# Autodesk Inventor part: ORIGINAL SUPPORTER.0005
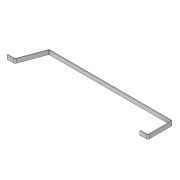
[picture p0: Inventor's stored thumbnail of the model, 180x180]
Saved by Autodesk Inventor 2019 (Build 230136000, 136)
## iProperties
Created: 2019-10
Part Number: ORIGINAL SUPPORTER.0005
Material: Generic
Document SubType Name: Sheet Metal
Designer: hp
Density: 1 g/cm^3
Sheet Metal Rule: Default_mm
Appearance: Default
Author: hp
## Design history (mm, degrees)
node "Face1"
  sketch "Sketch1"
    geometry: L1 (-53.057, 40.444)-(266.943, 40.444); L2 (266.943, 40.444)-(266.943, 30.444); L3 (266.943, 30.444)-(-53.057, 30.444); L4 (-53.057, 30.444)-(-53.057, 40.444); 1 further point
    constraints: 8 end point, 2 parallel, 1 horizontal, 1 perpendicular
    dimensions: "d3" = 320 distance of L2.end L3.end; "d4" = 10 distance of L1.end L2.end
node "Flange1"
node "Flange2"
node "Flange3"
node "Flange4"
body "Solid1"
face "Plate1" dims "d2" = 2 (= Thickness)
sketch "Sketch2"
  geometry: L1 through (-5, 0) direction (1, 0); L2 through (0, 32.5) direction (0, 1); L3 (0, 65)-(-10, 65); L4 (-10, 65)-(-10, 0)
  constraints: 6 end point, 1 horizontal, 1 perpendicular, 1 vertical
face "Plate2" dims "d2" = 2 (= Thickness), "d5" = 2 (= BendReliefWidth), "d6" = 1 (= BendReliefDepth), "d7" = 4 (= MinimumRemnant), "d8" = 2 (= TransitionRadius), "d9" = 65, "d10" = 90 deg, "d11" = 2 (= BendRadius), "d12" = 8 (= CornerReliefSize), "d13" = 2 (= GapSize), "d14" = 2 (= JacobiRadiusSize), "SeamGap" = 0.01
bend "Bend1" dims "d2" = 2 (= Thickness), "d5" = 2 (= BendReliefWidth), "d6" = 1 (= BendReliefDepth), "d7" = 4 (= MinimumRemnant), "d8" = 2 (= TransitionRadius), "d9" = 65, "d10" = 90 deg, "d11" = 2 (= BendRadius), "SeamGap" = 0.01
feature "Corner1" dims "d9" = 65, "d10" = 90 deg, "d12" = 8 (= CornerReliefSize), "d13" = 2 (= GapSize), "d14" = 2 (= JacobiRadiusSize)
sketch "Sketch3"
  geometry: L1 through (-5, 0) direction (1, 0); L2 through (0, 35) direction (0, 1); L3 (0, 70)-(-10, 70); L4 (-10, 70)-(-10, 0)
  constraints: 6 end point, 1 horizontal, 1 perpendicular, 1 vertical
face "Plate3" dims "d2" = 2 (= Thickness), "d15" = 2 (= BendReliefWidth), "d16" = 1 (= BendReliefDepth), "d17" = 4 (= MinimumRemnant), "d18" = 2 (= TransitionRadius), "d19" = 70, "d20" = 70 deg, "d21" = 2 (= BendRadius), "d22" = 8 (= CornerReliefSize), "d23" = 2 (= GapSize), "d24" = 2 (= JacobiRadiusSize), "SeamGap" = 0.01
bend "Bend2" dims "d2" = 2 (= Thickness), "d15" = 2 (= BendReliefWidth), "d16" = 1 (= BendReliefDepth), "d17" = 4 (= MinimumRemnant), "d18" = 2 (= TransitionRadius), "d19" = 70, "d20" = 70 deg, "d21" = 2 (= BendRadius), "SeamGap" = 0.01
feature "Corner2" dims "d19" = 70, "d20" = 70 deg, "d22" = 8 (= CornerReliefSize), "d23" = 2 (= GapSize), "d24" = 2 (= JacobiRadiusSize)
sketch "Sketch4"
  geometry: L1 through (0, -5) direction (0, 1); L2 through (-10, 0) direction (-1, 1.98e-33); L3 (-20, 0)-(-20, -10); L4 (-20, -10)-(0, -10)
  constraints: 6 end point, 1 horizontal, 1 perpendicular, 1 vertical
face "Plate4" dims "d2" = 2 (= Thickness), "d25" = 2 (= BendReliefWidth), "d26" = 1 (= BendReliefDepth), "d27" = 4 (= MinimumRemnant), "d28" = 2 (= TransitionRadius), "d29" = 20, "d30" = 70 deg, "d31" = 2 (= BendRadius), "d32" = 8 (= CornerReliefSize), "d33" = 2 (= GapSize), "d34" = 2 (= JacobiRadiusSize), "SeamGap" = 0.01
bend "Bend3" dims "d2" = 2 (= Thickness), "d25" = 2 (= BendReliefWidth), "d26" = 1 (= BendReliefDepth), "d27" = 4 (= MinimumRemnant), "d28" = 2 (= TransitionRadius), "d29" = 20, "d30" = 70 deg, "d31" = 2 (= BendRadius), "SeamGap" = 0.01
feature "Corner3" dims "d29" = 20, "d30" = 70 deg, "d32" = 8 (= CornerReliefSize), "d33" = 2 (= GapSize), "d34" = 2 (= JacobiRadiusSize)
sketch "Sketch5"
  geometry: L1 through (0, -5) direction (-0, 1); L2 through (-10, 0) direction (-1, 5.7e-33); L3 (-20, 0)-(-20, -10); L4 (-20, -10)-(0, -10)
  constraints: 6 end point, 1 horizontal, 1 perpendicular, 1 vertical
face "Plate5" dims "d2" = 2 (= Thickness), "d35" = 2 (= BendReliefWidth), "d36" = 1 (= BendReliefDepth), "d37" = 4 (= MinimumRemnant), "d38" = 2 (= TransitionRadius), "d39" = 20, "d40" = 90 deg, "d41" = 2 (= BendRadius), "d42" = 8 (= CornerReliefSize), "d43" = 2 (= GapSize), "d44" = 2 (= JacobiRadiusSize), "SeamGap" = 0.01
bend "Bend4" dims "d2" = 2 (= Thickness), "d35" = 2 (= BendReliefWidth), "d36" = 1 (= BendReliefDepth), "d37" = 4 (= MinimumRemnant), "d38" = 2 (= TransitionRadius), "d39" = 20, "d40" = 90 deg, "d41" = 2 (= BendRadius), "SeamGap" = 0.01
feature "Corner4" dims "d39" = 20, "d40" = 90 deg, "d42" = 8 (= CornerReliefSize), "d43" = 2 (= GapSize), "d44" = 2 (= JacobiRadiusSize)
other parameters: "Thickness" = 2 (derived), "BendRadius" = 2 (= Thickness), "BendReliefWidth" = 2 (= Thickness), "BendReliefDepth" = 1 (= 0.5 x Thickness), "CornerReliefSize" = 8 (= 4 x Thickness), "MinimumRemnant" = 4 (= 2 x Thickness), "TransitionRadius" = 2 (= BendRadius), "JacobiRadiusSize" = 2 (= BendRadius), "GapSize" = 2 (= Thickness)
